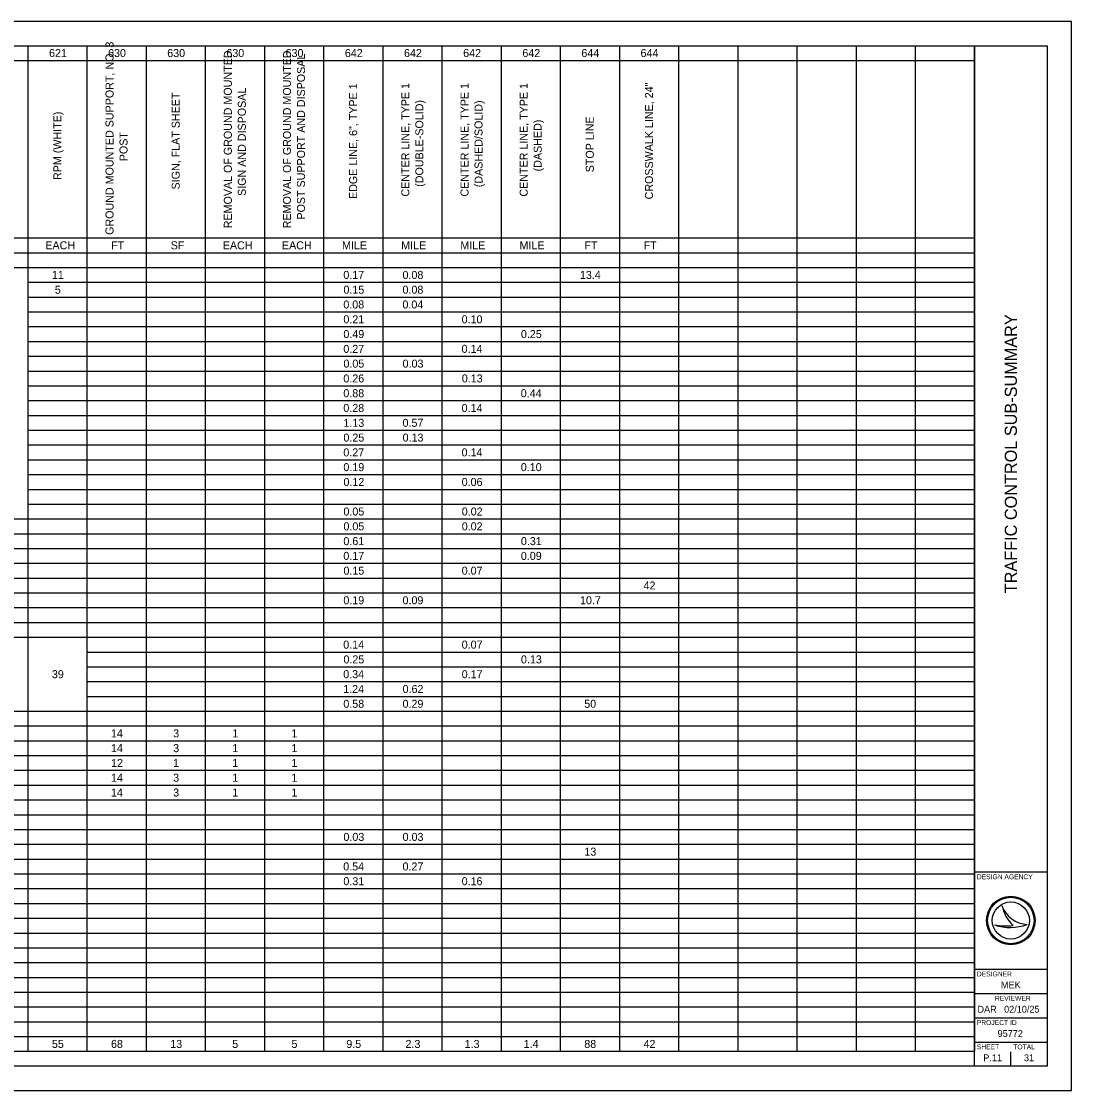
# Model space of a CAD drawing. Extents: x 0 to 34, y 0 to 22.
# Drawn here: x 12.39 to 34, y 0 to 22 of the extents above; entities that cross this region are included whole.
import ezdxf

# ---------------------------------------------------------------- set-up
doc = ezdxf.new("R2010")
doc.units = 0
for name, color, linetype in [('SH_Border', 7, 'Continuous'), ('SH_Cut_Line', 7, 'Continuous'), ('SH_Data', 7, 'Continuous'), ('SH_Text', 7, 'Continuous')]:
    doc.layers.add(name, color=color, linetype=linetype)

msp = doc.modelspace()

# ---------------------------------------------------------------- linework, layer by layer
at = {"layer": 'SH_Border'}
for p, q in [((32, 0.5), (32, 21.5)), ((32, 4.5), (33.5, 4.5)), ((32, 2.5), (33.5, 2.5)), ((32, 2), (33.5, 2)), ((32, 1.5), (33.5, 1.5)), ((32, 1), (33.5, 1))]:
    msp.add_line(p, q, dxfattribs=at)
msp.add_lwpolyline([(1.5, 21.5), (33.5, 21.5), (33.5, 0.5), (1.5, 0.5)], close=True, dxfattribs=at)
at = {"layer": 'SH_Cut_Line'}
msp.add_lwpolyline([(0, 0), (34, 0), (34, 22), (0, 22)], close=True, dxfattribs=at)
at = {"layer": 'SH_Data'}
for p, q in [((32.567, 3.81), (32.567, 3.81)), ((32.417, 3.41), (32.417, 3.41)), ((32.75, 3.5), (32.75, 3.5)), ((33.087, 3.419), (33.087, 3.419)), ((32.375, 0.675), (32.375, 0.675)), ((32.75, 0.5), (32.75, 0.8))]:
    msp.add_line(p, q, dxfattribs=at)
for radius in [0.5, 0.477, 0.477, 0.382]:
    msp.add_circle((32.75, 3.5), radius, dxfattribs=at)
for centre, radius, start, end in [((33.116, 3.998), 0.58, 198.9257, 198.9319), ((33.347, 3.97), 0.796, 191.6379, 191.6421), ((33.116, 3.998), 0.58, 198.9319, 267.1657), ((33.347, 3.97), 0.796, 191.6421, 226.0947), ((32.739, 4.37), 1.013, 251.4576, 290.0832), ((32.648, 4.654), 1.266, 259.4964, 259.4995), ((32.739, 4.37), 1.013, 251.4527, 251.4576), ((32.648, 4.654), 1.266, 259.4995, 276.6672)]:
    msp.add_arc(centre, radius, start, end, dxfattribs=at)
at = {"layer": 'SH_Text'}
for p, q in [((1.5, 21.5), (32, 21.5)), ((12.526, 21.5), (12.526, 0.809)), ((13.743, 21.5), (13.743, 0.809)), ((14.96, 21.5), (14.96, 0.809)), ((16.177, 21.5), (16.177, 0.809)), ((17.394, 21.5), (17.394, 0.809)), ((18.612, 21.5), (18.612, 0.809)), ((19.829, 21.5), (19.829, 0.809)), ((21.046, 21.5), (21.046, 0.809)), ((22.263, 21.5), (22.263, 0.809)), ((23.48, 21.5), (23.48, 0.809)), ((24.697, 21.5), (24.697, 0.809)), ((25.914, 21.5), (25.914, 0.809)), ((27.131, 21.5), (27.131, 0.809)), ((28.349, 21.5), (28.349, 0.809)), ((29.566, 21.5), (29.566, 0.809)), ((30.783, 21.5), (30.783, 0.809)), ((32, 21.5), (32, 0.809)), ((10.092, 21.196), (32, 21.196)), ((10.092, 17.544), (32, 17.544)), ((1.5, 17.24), (32, 17.24)), ((1.5, 16.936), (32, 16.936)), ((12.526, 16.631), (32, 16.631)), ((12.526, 16.327), (32, 16.327)), ((12.526, 16.023), (32, 16.023)), ((12.526, 15.719), (32, 15.719)), ((12.526, 15.414), (32, 15.414)), ((12.526, 15.11), (32, 15.11)), ((12.526, 14.806), (32, 14.806)), ((12.526, 14.501), (32, 14.501)), ((12.526, 14.197), (32, 14.197)), ((12.526, 13.893), (32, 13.893)), ((12.526, 13.589), (32, 13.589)), ((12.526, 13.284), (32, 13.284)), ((12.526, 12.98), (32, 12.98)), ((12.526, 12.676), (32, 12.676)), ((12.526, 12.371), (32, 12.371)), ((12.526, 12.067), (32, 12.067)), ((1.5, 11.763), (32, 11.763)), ((1.5, 11.459), (32, 11.459)), ((1.5, 11.154), (32, 11.154)), ((1.5, 10.85), (32, 10.85)), ((1.5, 10.546), (32, 10.546)), ((1.5, 10.241), (32, 10.241)), ((1.5, 9.937), (32, 9.937)), ((1.5, 9.633), (32, 9.633)), ((1.5, 9.329), (32, 9.329)), ((13.743, 9.024), (32, 9.024)), ((13.743, 8.72), (32, 8.72)), ((13.743, 8.416), (32, 8.416)), ((13.743, 8.112), (32, 8.112)), ((1.5, 7.807), (32, 7.807)), ((1.5, 7.503), (32, 7.503)), ((1.5, 7.199), (32, 7.199)), ((1.5, 6.894), (32, 6.894)), ((1.5, 6.59), (32, 6.59)), ((1.5, 6.286), (32, 6.286)), ((1.5, 5.982), (32, 5.982)), ((1.5, 5.677), (32, 5.677)), ((1.5, 5.373), (32, 5.373)), ((1.5, 5.069), (32, 5.069)), ((1.5, 4.764), (32, 4.764)), ((1.5, 4.46), (32, 4.46)), ((1.5, 4.156), (32, 4.156)), ((1.5, 3.852), (32, 3.852)), ((1.5, 3.547), (32, 3.547)), ((1.5, 3.243), (32, 3.243)), ((1.5, 2.939), (32, 2.939)), ((1.5, 2.634), (32, 2.634)), ((1.5, 2.33), (32, 2.33)), ((1.5, 2.026), (32, 2.026)), ((1.5, 1.722), (32, 1.722)), ((1.5, 1.417), (32, 1.417)), ((1.5, 1.113), (32, 1.113)), ((1.5, 0.809), (32, 0.809))]:
    msp.add_line(p, q, dxfattribs=at)

# ---------------------------------------------------------------- texts
at = {"layer": 'SH_Data'}
msp.add_text('TRAFFIC CONTROL SUB-SUMMARY', height=0.25, rotation=90, dxfattribs=at).set_placement((32.875, 10.234))
for s, height, p in [('DESIGN AGENCY', 0.1, (32.05, 4.35)), ('DESIGNER', 0.1, (32.05, 2.35)), ('MEK', 0.14, (32.547, 2.105)), ('REVIEWER', 0.1, (32.422, 1.85)), ('DAR', 0.14, (32.064, 1.605)), ('02/10/25', 0.14, (32.611, 1.605)), ('PROJECT ID', 0.1, (32.05, 1.35)), ('95772', 0.14, (32.477, 1.105)), ('SHEET', 0.1, (32.05, 0.85)), ('TOTAL', 0.1, (32.8, 0.85)), ('P.11', 0.14, (32.184, 0.605)), ('31', 0.14, (33.019, 0.605))]:
    msp.add_text(s, height=height, dxfattribs=at).set_placement(p)
at = {"layer": 'SH_Text'}
for s, height, p in [('GROUND MOUNTED SUPPORT, NO. 3 ', 0.16467, (14.29, 17.607)), ('REMOVAL OF GROUND MOUNTED ', 0.16467, (16.724, 17.743)), ('REMOVAL OF GROUND MOUNTED ', 0.16467, (17.941, 17.743)), ('POST SUPPORT AND DISPOSAL', 0.16467, (18.229, 17.922)), ('EDGE LINE, 6", TYPE 1', 0.16467, (19.302, 18.346)), ('CENTER LINE, TYPE 1                    ', 0.16467, (20.375, 18.395)), ('CENTER LINE, TYPE 1 ', 0.16467, (21.593, 18.395)), ('CENTER LINE, TYPE 1                               ', 0.16467, (22.81, 18.395)), ('CROSSWALK LINE, 24"', 0.16467, (25.388, 18.337)), ('SIGN, FLAT SHEET', 0.16467, (15.651, 18.542)), ('SIGN AND DISPOSAL', 0.16467, (17.012, 18.409)), ('(DOUBLE-SOLID)', 0.16467, (20.664, 18.596)), ('(DASHED/SOLID)', 0.16467, (21.881, 18.588)), ('RPM (WHITE)', 0.16467, (13.217, 18.737)), ('STOP LINE', 0.1647, (24.171, 18.895)), ('(DASHED)', 0.1647, (23.098, 18.914)), ('POST', 0.1647, (14.578, 19.123))]:
    msp.add_text(s, height=height, rotation=90, dxfattribs=at).set_placement(p)
for s, height, p in [('621', 0.1647, (12.963, 21.266)), ('630', 0.1647, (14.178, 21.266)), ('630', 0.1647, (15.395, 21.266)), ('630', 0.1647, (16.612, 21.266)), ('630', 0.1647, (17.83, 21.266)), ('642', 0.1647, (19.049, 21.266)), ('642', 0.1647, (20.266, 21.266)), ('642', 0.1647, (21.483, 21.266)), ('642', 0.1647, (22.701, 21.266)), ('644', 0.1647, (23.915, 21.266)), ('644', 0.1647, (25.132, 21.266)), ('EACH', 0.1647, (12.887, 17.31)), ('FT', 0.1647, (14.242, 17.31)), ('SF', 0.1647, (15.466, 17.31)), ('EACH', 0.1647, (16.538, 17.31)), ('EACH', 0.1647, (17.755, 17.31)), ('MILE', 0.1647, (18.991, 17.31)), ('MILE', 0.1647, (20.208, 17.31)), ('MILE', 0.1647, (21.425, 17.31)), ('MILE', 0.1647, (22.642, 17.31)), ('FT', 0.1647, (23.979, 17.31)), ('FT', 0.1647, (25.196, 17.31)), ('11', 0.1647, (13.022, 16.701)), ('0.17', 0.1647, (19.018, 16.701)), ('0.08', 0.1647, (20.235, 16.701)), ('13.4', 0.1647, (23.885, 16.701)), ('5', 0.165, (13.082, 16.397)), ('0.15', 0.1647, (19.02, 16.397)), ('0.08', 0.1647, (20.235, 16.397)), ('0.08', 0.1647, (19.018, 16.093)), ('0.04', 0.1647, (20.234, 16.093)), ('0.21', 0.1647, (19.019, 15.788)), ('0.10', 0.1647, (21.451, 15.788)), ('0.49', 0.1647, (19.019, 15.484)), ('0.25', 0.1647, (22.671, 15.484)), ('0.27', 0.1647, (19.018, 15.18)), ('0.14', 0.1647, (21.451, 15.18)), ('0.05', 0.1647, (19.02, 14.876)), ('0.03', 0.1647, (20.237, 14.876)), ('0.26', 0.1647, (19.018, 14.571)), ('0.13', 0.1647, (21.455, 14.571)), ('0.88', 0.1647, (19.018, 14.267)), ('0.44', 0.1647, (22.668, 14.267)), ('0.28', 0.1647, (19.018, 13.963)), ('0.14', 0.1647, (21.451, 13.963)), ('1.13', 0.1647, (19.02, 13.658)), ('0.57', 0.1647, (20.236, 13.658)), ('0.25', 0.1647, (19.02, 13.354)), ('0.13', 0.1647, (20.237, 13.354)), ('0.27', 0.1647, (19.018, 13.05)), ('0.14', 0.1647, (21.451, 13.05)), ('0.19', 0.1647, (19.019, 12.746)), ('0.10', 0.1647, (22.669, 12.746)), ('0.12', 0.1647, (19.02, 12.441)), ('0.06', 0.1647, (21.452, 12.441)), ('0.05', 0.1647, (19.02, 11.833)), ('0.02', 0.1647, (21.454, 11.833)), ('0.05', 0.1647, (19.02, 11.528)), ('0.02', 0.1647, (21.454, 11.528)), ('0.61', 0.1647, (19.019, 11.224)), ('0.31', 0.1647, (22.671, 11.224)), ('0.17', 0.1647, (19.018, 10.92)), ('0.09', 0.1647, (22.67, 10.92)), ('0.15', 0.1647, (19.02, 10.616)), ('0.07', 0.1647, (21.453, 10.616)), ('42', 0.1647, (25.194, 10.311)), ('0.19', 0.1647, (19.019, 10.007)), ('0.09', 0.1647, (20.236, 10.007)), ('10.7', 0.1647, (23.887, 10.007)), ('0.14', 0.1647, (19.016, 9.094)), ('0.07', 0.1647, (21.453, 9.094)), ('0.25', 0.1647, (19.02, 8.79)), ('0.13', 0.1647, (22.672, 8.79)), ('39', 0.1647, (13.022, 8.486)), ('0.34', 0.1647, (19.016, 8.486)), ('0.17', 0.1647, (21.453, 8.486)), ('1.24', 0.1647, (19.016, 8.181)), ('0.62', 0.1647, (20.237, 8.181)), ('0.58', 0.1647, (19.018, 7.877)), ('0.29', 0.1647, (20.236, 7.877)), ('50', 0.1647, (23.974, 7.877)), ('14', 0.1647, (14.237, 7.268)), ('3', 0.165, (15.517, 7.268)), ('1', 0.165, (16.733, 7.268)), ('1', 0.165, (17.95, 7.268)), ('14', 0.1647, (14.237, 6.964)), ('3', 0.165, (15.517, 6.964)), ('1', 0.165, (16.733, 6.964)), ('1', 0.165, (17.95, 6.964)), ('12', 0.1647, (14.24, 6.66)), ('1', 0.165, (15.516, 6.66)), ('1', 0.165, (16.733, 6.66)), ('1', 0.165, (17.95, 6.66)), ('14', 0.1647, (14.237, 6.356)), ('3', 0.165, (15.517, 6.356)), ('1', 0.165, (16.733, 6.356)), ('1', 0.165, (17.95, 6.356)), ('14', 0.1647, (14.237, 6.051)), ('3', 0.165, (15.517, 6.051)), ('1', 0.165, (16.733, 6.051)), ('1', 0.165, (17.95, 6.051)), ('0.03', 0.1647, (19.02, 5.138)), ('0.03', 0.1647, (20.237, 5.138)), ('13', 0.1647, (23.977, 4.834)), ('0.54', 0.1647, (19.016, 4.53)), ('0.27', 0.1647, (20.236, 4.53)), ('0.31', 0.1647, (19.019, 4.226)), ('0.16', 0.1647, (21.452, 4.226)), ('55', 0.1647, (13.023, 0.878)), ('68', 0.1647, (14.238, 0.878)), ('13', 0.1647, (15.457, 0.878)), ('5', 0.165, (16.733, 0.878)), ('5', 0.165, (17.951, 0.878)), ('9.5', 0.1647, (19.079, 0.878)), ('2.3', 0.1647, (20.297, 0.878)), ('1.3', 0.1647, (21.514, 0.878)), ('1.4', 0.1647, (22.727, 0.878)), ('88', 0.1647, (23.975, 0.878)), ('42', 0.1647, (25.194, 0.878))]:
    msp.add_text(s, height=height, dxfattribs=at).set_placement(p)

doc.saveas('drawing.dxf')
